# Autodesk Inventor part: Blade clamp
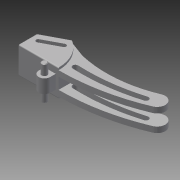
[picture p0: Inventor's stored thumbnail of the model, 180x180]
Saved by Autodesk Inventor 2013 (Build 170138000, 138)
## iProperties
Created: 2008-06
Part Number: Blade clamp
Document SubType Name: Modeling
Designer: tangg
Density: 7.85 g/cm^3
Mass: 7.32781 g
Surface Area: 54.7426 cm^2
Volume: 7.32781 cm^3
Stock Number: Blade clamp
Material: Steel
Author: tangg
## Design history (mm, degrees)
sketch "Sketch14"
  geometry: L1 (7.937, 3.175)-(7.937, 0); L2 (1.587, 0)-(1.587, 3.175); L3 (7.937, 0)-(1.587, 0); L4 (7.937, 0)-(1.587, 0) reference; C1 r 1.587 at (4.762, 3.175); A1 r 3.175 centre (4.762, 3.175) between (7.937, 3.175) and (1.587, 3.175); 1 further point
  constraints: 8 end point, 2 centre point, 2 horizontal alignment, 2 point on circle, 1 coincident, 1 horizontal, 1 vertical, 1 other
  dimensions: "d57" = 6.35 distance of L1.end L2.start; "d58" = 3.175 radius of A1; "d59" = 3.175 diameter of C1
extrude "Extrusion18" join sketch "Sketch14" stored distance "d68" = 7.62; taper "d69" = 0 deg
sketch "Sketch30"
  geometry: L1 (0, 0)-(22.663, 0); L2 (22.663, 0)-(22.663, -10.474); L3 (22.663, -10.474)-(9.865, -17.21); L4 (9.865, -17.21)-(0.414, -13.728); L5 (0, 0)-(-3.829, 0); L6 (18.185, -6.295)-(8.665, -11.306); L7 (19.215, -8.324)-(9.724, -13.319); L8 (1.587, 0)-(7.937, 0) reference; L9 (0, -114.3)-(-43.989, -8.804); A1 r 1.137 centre (18.7, -7.309) between (19.215, -8.324) and (18.185, -6.295); A2 r 1.137 centre (9.194, -12.312) between (8.665, -11.306) and (9.724, -13.319); A3 r 114.3 centre (0, -114.3) between (0, 0) and (-43.989, -8.804); A4 r 66.779 centre (-14.826, -78.745) between (0.414, -13.728) and (-40.526, -17.11); A5 r 4.499 centre (-42.258, -12.957) between (-43.989, -8.804) and (-40.526, -17.11)
  constraints: 16 end point, 10 point on circle, 5 centre point, 2 point on line, 1 collinear, 1 parallel, 1 tangent, 1 vertical alignment
  dimensions: "d110" = 114.3 radius of A3
extrude "Extrusion28" join sketch "Sketch30" stored distance "d102" = 15.24; taper "d103" = 0 deg
sketch "Sketch36"
  geometry: L1 (19.244, -8.308)-(9.724, -13.319); L2 (18.185, -6.295)-(8.665, -11.306); A1 r 1.137 centre (18.715, -7.302) between (19.244, -8.308) and (18.185, -6.295); A2 r 1.137 centre (9.194, -12.313) between (8.665, -11.306) and (9.724, -13.319); 1 further point
  constraints: 4 end point, 4 point on circle, 2 centre point, 1 parallel
extrude "Extrusion29" cut sketch "Sketch36" stored distance "d104" = 15.24; taper "d105" = 0 deg
sketch "Sketch38"
  geometry: A1 r 106.726 centre (-7.616, -112.905) between (-1.587, -6.35) and (-39.688, -11.113); 2 further points
  constraints: 2 point on circle, 1 centre point
extrude_surface "ExtrusionSrf3" sketch "Sketch38" dims "d106" = 15.24, "d107" = 0
thicken "Thicken2" dims "d108" = 3
fillet "Fillet5" dims "d109" = 1.5
sketch "Sketch33"
  geometry: L1 (18.185, -6.295)-(8.665, -11.306) reference; L2 (9.724, -13.319)-(19.244, -8.308) reference; L3 (7.937, 0)-(22.663, 0) reference; L4 (22.663, 0)-(22.663, -10.474) reference; L5 (22.663, -10.474)-(9.865, -17.21) reference; L6 (9.865, -17.21)-(0.414, -13.728) reference; L7 (0, 0)-(1.587, 0) reference; L8 (1.587, 0)-(1.587, 3.175) reference; L9 (7.937, 3.175)-(7.937, 0) reference; L10 (0, 0)-(0, -13.632); C1 r 1.587 at (4.762, 3.175) reference; A1 r 1.137 centre (18.715, -7.302) between (19.244, -8.308) and (18.185, -6.295) reference; A2 r 1.137 centre (9.194, -12.313) between (8.665, -11.306) and (9.724, -13.319) reference; A3 r 66.779 centre (-14.826, -78.745) between (0.414, -13.728) and (-40.526, -17.11) reference; A4 r 4.499 centre (-42.258, -12.957) between (-43.989, -8.804) and (-40.526, -17.11) reference; A5 r 114.3 centre (0, -114.3) between (0, 0) and (-43.989, -8.804) reference; A6 r 3.175 centre (4.762, 3.175) between (7.937, 3.175) and (1.587, 3.175) reference; A7 r 1.5 centre (-38.254, -10.672) between (-38.684, -9.235) and (-37.823, -12.109) reference; A8 r 105.226 centre (-7.616, -112.905) between (-3.149, -7.774) and (-37.823, -12.109) reference; A9 r 1.5 centre (-3.086, -6.276) between (-3.149, -7.774) and (-3.022, -4.777) reference; A10 r 106.726 centre (-7.616, -112.905) between (-1.587, -6.35) and (-39.688, -11.113) reference; A11 r 108.226 centre (-7.616, -112.905) between (-3.022, -4.777) and (-38.684, -9.235) reference
  constraints: 2 end point, 1 point on circle
extrude "Extrusion25" cut sketch "Sketch33" stored distance "d93" = 6.35; taper "d94" = 0 deg
sketch "Sketch41"
  geometry: L1 (-0.414, -13.728)-(-9.865, -17.21) reference; L2 (-22.663, 0)-(0, 0) reference; A1 r 114.3 centre (0, -114.3) between (43.989, -8.804) and (0, 0) reference; A2 r 4.499 centre (42.258, -12.957) between (40.526, -17.11) and (43.989, -8.804) reference; A3 r 66.779 centre (14.826, -78.745) between (40.526, -17.11) and (-0.414, -13.728) reference; A4 r 19.944 centre (-19.944, 0) between (-9.865, -17.21) and (0, 0)
  constraints: 2 point on circle, 1 centre point, 1 point on line
extrude "Extrusion30" cut sketch "Sketch41" distance "d111" = 1.27; taper "d112" = 0 deg
mirror "Mirror2"
sketch "Sketch44"
  geometry: A1 r 105.226 centre (7.616, -112.905) between (37.823, -12.109) and (3.149, -7.774) reference; A2 r 1.5 centre (3.086, -6.276) between (3.022, -4.777) and (3.149, -7.774) reference; A3 r 1.5 centre (38.254, -10.672) between (37.823, -12.109) and (38.684, -9.235) reference; A4 r 108.226 centre (7.616, -112.905) between (38.684, -9.235) and (3.022, -4.777) reference; 1 further point
sketch "Sketch45"
  geometry: C1 r 1.524 at (4.763, 3.175); 1 further point
  constraints: 1 centre point
  dimensions: "d114" = 3.048 diameter of C1
extrude "Extrusion31" join sketch "Sketch45" stored distance "d115" = 19.05; taper "d116" = 0 deg
chamfer "Chamfer1" distance "d117" = 0.3175; stored, may be unused: second distance "d118" = 3.175, angle "d119" = 45 deg
fillet "Fillet6" dims "d120" = 0.635
sketch "Sketch47"
  geometry: L1 (-1.588, 7.366)-(-11.113, 7.366); L2 (-11.113, 7.366)-(-11.113, 6.604); L3 (-11.113, 6.604)-(-1.587, 6.604); L4 (-1.587, 6.604)-(-1.588, 7.366); 2 further points
  constraints: 8 end point, 1 horizontal alignment, 1 midpoint
  dimensions: "d127" = 0.762 distance of L3.end L1.start; "d128" = 9.525 distance of L2.end L3.end
extrude "Extrusion33" cut sketch "Sketch47" distance "d124" = 17.78; taper "d125" = 0 deg
body "Solid1"
body "Srf1"
workplane "Work Plane6"
node "Project Cut Edges2"
